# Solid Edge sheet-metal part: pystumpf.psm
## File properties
Author: Administrator
Template: Normal.psm
Last saved by: Administrator
Revision: 2
Application: Solid Edge
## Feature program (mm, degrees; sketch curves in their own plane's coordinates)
base tab "unnamed BaseTab 1"
contour flange "unnamed ContourFlange 1"
contour flange "unnamed ContourFlange 2"
